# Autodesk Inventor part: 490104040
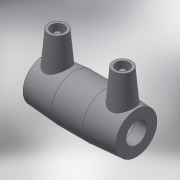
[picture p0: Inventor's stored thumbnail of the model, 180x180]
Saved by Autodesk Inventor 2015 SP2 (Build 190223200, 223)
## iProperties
Created: 2017-06
Part Number: 490104040
Material: Generic
Description: PLASSON COUPLER 40-40
Document SubType Name: Modeling
Designer: KIM
Mass: 55.0731 g
Surface Area: 148.067 cm^2
Volume: 55.0731 cm^3
Density: 1 g/cm^3
Appearance: Default
Author: KIM
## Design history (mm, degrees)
derived "490104.ipt"
feature "Solid1::490104.ipt"
tag "TaggingFeature1"
body "Solid1"
other parameters: "d0" = 97, "d2" = 56, "d3" = 47, "d4" = 32.33333, "d5" = 50.4, "d6" = 38, "d8" = 168 deg, "d10" = 18.8, "d11" = 6.26667, "d13" = 97, "d14" = 17.6296, "d15" = 47, "d16" = 47, "d17" = 38, "d19" = 3.52592, "d20" = 168 deg, "d22" = 52.64, "d23" = 56, "d24" = 51.0608, "d25" = 135 deg, "d26" = 38.8, "d27" = 135 deg, "d29" = 46, "d30" = 14, "d31" = 33.95, "d34" = 5 deg, "d35" = 15, "d39" = 5 deg, "d41" = 4, "d42" = 14, "d43" = 0, "d45" = 4, "d46" = 14, "d47" = 0, "d48" = 3, "d49" = 0, "d50" = 3, "d51" = 0, "d52" = 13.63, "d53" = 3.4075, "L_" = 97, "L_1" = 47, "D_" = 56, "A_" = 46, "d_2" = 12
